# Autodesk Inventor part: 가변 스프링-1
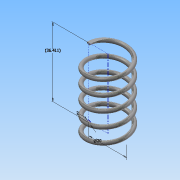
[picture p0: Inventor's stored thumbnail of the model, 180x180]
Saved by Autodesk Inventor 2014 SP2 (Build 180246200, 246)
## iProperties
Created: 2016-01
Part Number: 가변 스프링-1
Material: 스테인레스 스틸
Document SubType Name: Modeling
Designer: Administrator
Density: 8.08 g/cm^3
Appearance: 반연마
Mass: 7.88156 g
Surface Area: 19.7613 cm^2
Volume: 0.975441 cm^3
Author: Administrator
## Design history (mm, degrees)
sketch "스케치2"
  geometry: L1 (0, 0)-(10, 0); L2 (10, 0)-(10, 36.411); L3 (10, 36.411)-(0, 36.411); L4 (0, 36.411)-(0, 0); C1 r 1 at (10, 0)
  constraints: 8 end point, 2 parallel, 1 centre point, 1 coincident, 1 horizontal, 1 perpendicular
  dimensions: "d0" = 2 diameter of C1; "d1" = 20 diameter of L2 L4; "d2" = 36.4112 distance between parallel lines of L3 L1 (derived)
feature "코일1" pitch "d3" = 10; turns "d5" = 5; dims "d4" = 36.4112 (= d2), "d6" = 0, angle "d7" = 90 deg, angle "d8" = 90 deg, "d9" = 0, "d10" = 0
sketch "스케치3"
  geometry: L1 (-11, 0)-(-9, 0) reference; 1 further point
  constraints: 1 horizontal alignment
extrude "돌출1" cut sketch "스케치3" stored distance "d11" = 10; taper "d12" = 0 deg
node "작업 평면1"
sketch "스케치4"
  geometry: L1 (1, 0)-(-1, 0) reference; 1 further point
  constraints: 1 horizontal alignment
extrude "돌출2" cut sketch "스케치4" stored distance "d14" = 10; taper "d15" = 0 deg
node "솔리드1"
node "절단 모서리 투영1"
node "절단 모서리 투영2"
other parameters: "d13" = 0
